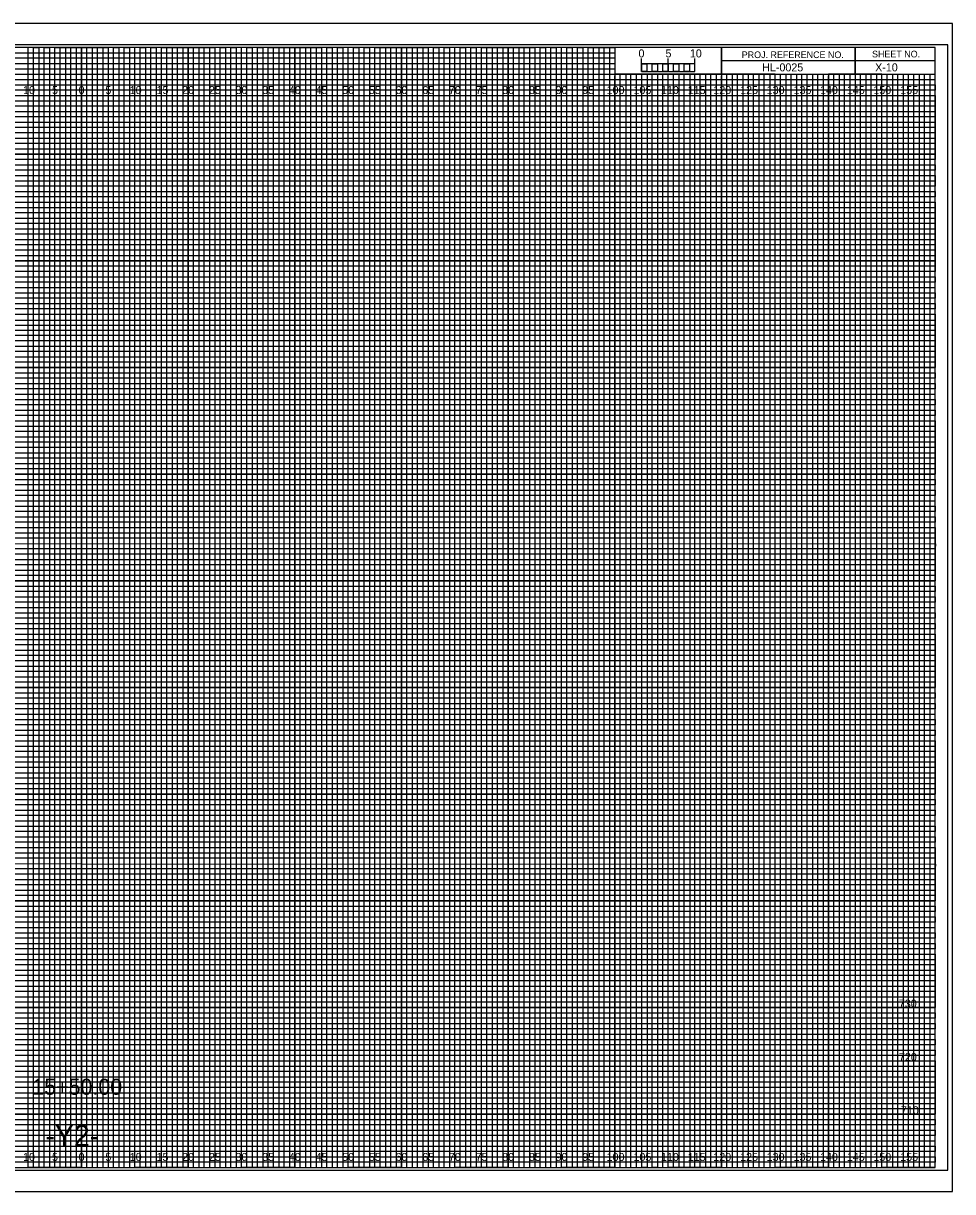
# Model space of a CAD drawing. Extents: x -13 to 323, y -5 to 654.
# Drawn here: x 149.1 to 323.3, y 435.5 to 654.5 of the extents above; entities that cross this region are included whole.
import ezdxf

# ---------------------------------------------------------------- set-up
doc = ezdxf.new("R2010")
doc.units = 0
for name, color, linetype in [('Exist CMT Pavement', 7, 'Continuous'), ('Exist Cross Section Cell', 7, 'Continuous'), ('Exist XS Center Line Elevation Label', 7, 'Continuous'), ('Exist XS Ground Line', 7, 'Continuous'), ('Prop CMT Pvmt Course 1', 7, 'Continuous'), ('Prop CMT Pvmt Course 1 Wedge', 7, 'Continuous'), ('Prop CMT Pvmt Course 2', 7, 'Continuous'), ('Prop CMT Pvmt Course 3', 7, 'Continuous'), ('Prop CMT Pvmt Surface', 7, 'Continuous'), ('Prop CMT Pvmt Surface Shoulder', 7, 'Continuous'), ('Prop CMT Pvmt Wedge Surface 1', 7, 'Continuous'), ('Prop CMT Shld Paved Course 1', 7, 'Continuous'), ('Prop CMT Shld Paved Course 2', 7, 'Continuous'), ('Prop CMT Shld Paved Course 3', 7, 'Continuous'), ('Prop CMT Slope Grass', 7, 'Continuous'), ('Prop CMT Subgrade Earthwork', 7, 'Continuous'), ('Scratch_Level_1', 7, 'Continuous')]:
    doc.layers.add(name, color=color, linetype=linetype)

msp = doc.modelspace()

# ---------------------------------------------------------------- linework, layer by layer
at = {"layer": 'Exist XS Center Line Elevation Label'}
for points in [[(145, 440), (155, 440), (155, 650), (165, 650), (165, 440), (175, 440), (175, 650), (185, 650), (185, 440), (195, 440), (195, 650), (205, 650), (205, 440), (215, 440), (215, 650), (225, 650), (225, 440), (235, 440), (235, 650), (245, 650), (245, 440), (255, 440), (255, 650), (259.93, 650), (260, 650), (260, 645), (264.99, 645), (264.99, 440), (275, 440), (275, 645), (285, 645), (285, 440), (295, 440), (295, 645), (305, 645), (305, 440), (315, 440), (315, 645)], [(0, 645), (275, 645)], [(0, 625), (320, 625), (320, 635), (0, 635)], [(0, 605), (320, 605), (320, 615), (0, 615)], [(0, 585), (320, 585), (320, 595), (0, 595)], [(0, 565), (320, 565), (320, 575), (0, 575)], [(0, 545), (320, 545), (320, 555), (0, 555)], [(0, 525), (320, 525), (320, 535), (0, 535)], [(0, 505), (320, 505), (320, 515), (0, 515)], [(0, 485), (320, 485), (320, 495), (0, 495)], [(0, 465), (320, 465), (320, 475), (0, 475)], [(0, 445), (320, 445), (320, 455), (0, 455)]]:
    msp.add_lwpolyline(points, dxfattribs=at)
at = {"layer": 'Exist XS Ground Line'}
for p, q in [((150, 650), (140, 650)), ((150, 440), (150, 650)), ((170, 650), (160, 650)), ((160, 650), (160, 440)), ((170, 440), (170, 650)), ((190, 650), (180, 650)), ((180, 650), (180, 440)), ((190, 440), (190, 650)), ((210, 650), (200, 650)), ((200, 650), (200, 440)), ((210, 440), (210, 650)), ((230, 650), (220, 650)), ((220, 650), (220, 440)), ((230, 440), (230, 650)), ((250, 650), (240, 650)), ((240, 650), (240, 440)), ((250, 440), (250, 650)), ((260, 650), (260, 440)), ((270, 440), (270, 645)), ((290, 645), (280, 645)), ((280, 645), (280, 440)), ((290, 440), (290, 645)), ((310, 645), (300, 645)), ((300, 645), (300, 440)), ((310, 440), (310, 645)), ((160, 440), (150, 440)), ((180, 440), (170, 440)), ((200, 440), (190, 440)), ((220, 440), (210, 440)), ((240, 440), (230, 440)), ((260, 440), (250, 440)), ((280, 440), (270, 440)), ((300, 440), (290, 440)), ((320, 440), (310, 440)), ((320, 440), (320, 440))]:
    msp.add_line(p, q, dxfattribs=at)
for points in [[(0, 640), (320, 640), (320, 630), (0, 630)], [(0, 620), (320, 620), (320, 610), (0, 610)], [(0, 600), (320, 600), (320, 590), (0, 590)], [(0, 580), (320, 580), (320, 570), (0, 570)], [(0, 560), (320, 560), (320, 550), (0, 550)], [(0, 540), (320, 540), (320, 530), (0, 530)], [(0, 520), (320, 520), (320, 510), (0, 510)], [(0, 500), (320, 500), (320, 490), (0, 490)], [(0, 480), (320, 480), (320, 470), (0, 470)], [(0, 460), (320, 460), (320, 450), (0, 450)]]:
    msp.add_lwpolyline(points, dxfattribs=at)
at = {"layer": 'Prop CMT Pvmt Course 2'}
msp.add_lwpolyline([(-13.4, 435.5), (323.3, 435.5), (323.3, 654.5), (-13.4, 654.5)], close=True, dxfattribs=at)
at = {"layer": 'Prop CMT Pvmt Course 3'}
msp.add_lwpolyline([(-10.8, 439.5), (322.4, 439.5), (322.4, 650.5), (-10.8, 650.5)], close=True, dxfattribs=at)
msp.add_lwpolyline([(-10.8, 439.5), (322.4, 439.5), (322.4, 650.5), (-10.8, 650.5)], close=True, dxfattribs=at)
at = {"layer": 'Prop CMT Pvmt Surface'}
for p, q in [((323.3, 654.5), (-13.4, 654.5)), ((323.3, 654.5), (-13.4, 654.5)), ((-13.4, 435.5), (323.3, 435.5)), ((-13.4, 435.5), (323.3, 435.5))]:
    msp.add_line(p, q, dxfattribs=at)
at = {"layer": 'Prop CMT Shld Paved Course 1'}
for p, q in [((305, 650), (305, 645)), ((305, 645), (305, 650)), ((280, 647.5), (280, 645)), ((320, 647.49), (280, 647.49)), ((280, 645), (320, 645))]:
    msp.add_line(p, q, dxfattribs=at)
for points in [[(320, 650), (0, 650), (0, 440), (320, 440)], [(280, 650), (260, 650), (260, 645.03), (280, 645.03)], [(320, 650), (280, 650), (280, 645), (320, 645)]]:
    msp.add_lwpolyline(points, close=True, dxfattribs=at)
at = {"layer": 'Prop CMT Shld Paved Course 2'}
for p, q in [((267, 645), (266.01, 645)), ((266.01, 645), (266.01, 440)), ((267, 440), (267, 645)), ((269, 645), (268, 645)), ((268, 645), (268, 440)), ((269, 440), (269, 645)), ((266.01, 440), (265, 440)), ((268, 440), (267, 440))]:
    msp.add_line(p, q, dxfattribs=at)
for points in [[(150, 440), (151, 440), (151, 650), (152, 650), (152, 440)], [(152, 440), (153, 440), (153, 650), (154, 650), (154, 440)], [(155, 440), (156, 440), (156, 650), (157, 650), (157, 440)], [(157, 440), (158, 440), (158, 650), (159, 650), (159, 440)], [(160, 440), (161, 440), (161, 650), (162, 650), (162, 440)], [(162, 440), (163, 440), (163, 650), (164, 650), (164, 440)], [(165, 440), (166, 440), (166, 650), (167, 650), (167, 440)], [(167, 440), (168, 440), (168, 650), (169, 650), (169, 440)], [(170, 440), (171, 440), (171, 650), (172, 650), (172, 440)], [(172, 440), (173, 440), (173, 650), (174, 650), (174, 440)], [(175, 440), (176, 440), (176, 650), (177, 650), (177, 440)], [(177, 440), (178, 440), (178, 650), (179, 650), (179, 440)], [(180, 440), (181, 440), (181, 650), (182, 650), (182, 440)], [(182, 440), (183, 440), (183, 650), (184, 650), (184, 440)], [(185, 440), (186, 440), (186, 650), (187, 650), (187, 440)], [(187, 440), (188, 440), (188, 650), (189, 650), (189, 440)], [(190, 440), (191, 440), (191, 650), (192, 650), (192, 440)], [(192, 440), (193, 440), (193, 650), (194, 650), (194, 440)], [(195, 440), (196, 440), (196, 650), (197, 650), (197, 440)], [(197, 440), (198, 440), (198, 650), (199, 650), (199, 440)], [(200, 440), (201, 440), (201, 650), (202, 650), (202, 440)], [(202, 440), (203, 440), (203, 650), (204, 650), (204, 440)], [(205, 440), (206, 440), (206, 650), (207, 650), (207, 440)], [(207, 440), (208, 440), (208, 650), (209, 650), (209, 440)], [(210, 440), (211, 440), (211, 650), (212, 650), (212, 440)], [(212, 440), (213, 440), (213, 650), (214, 650), (214, 440)], [(215, 440), (216, 440), (216, 650), (217, 650), (217, 440)], [(217, 440), (218, 440), (218, 650), (219, 650), (219, 440)], [(220, 440), (221, 440), (221, 650), (222, 650), (222, 440)], [(222, 440), (223, 440), (223, 650), (224, 650), (224, 440)], [(225, 440), (226, 440), (226, 650), (227, 650), (227, 440)], [(227, 440), (228, 440), (228, 650), (229, 650), (229, 440)], [(230, 440), (231, 440), (231, 650), (232, 650), (232, 440)], [(232, 440), (233, 440), (233, 650), (234, 650), (234, 440)], [(235, 440), (236, 440), (236, 650), (237, 650), (237, 440)], [(237, 440), (238, 440), (238, 650), (239, 650), (239, 440)], [(240, 440), (241, 440), (241, 650), (242, 650), (242, 440)], [(242, 440), (243, 440), (243, 650), (244, 650), (244, 440)], [(245, 440), (246, 440), (246, 650), (247, 650), (247, 440)], [(247, 440), (248, 440), (248, 650), (249, 650), (249, 440)], [(250, 440), (251, 440), (251, 650), (252, 650), (252, 440)], [(252, 440), (253, 440), (253, 650), (254, 650), (254, 440)], [(255, 440), (256, 440), (256, 650), (257, 650), (257, 440)], [(257, 440), (258, 440), (258, 650), (259, 650), (259, 440)], [(260, 440), (261, 440), (261, 645), (262.02, 645), (262.02, 440)], [(262, 440), (263, 440), (263, 645), (263.99, 645), (263.99, 440)], [(270, 440), (270.98, 440), (270.98, 645), (272, 645), (272, 440)], [(272, 440), (273, 440), (273, 645), (274.05, 645), (274.05, 440)], [(275, 440), (276, 440), (276, 645), (277, 645), (277, 440)], [(277, 440), (278, 440), (278, 645), (279, 645), (279, 440)], [(280, 440), (281, 440), (281, 645), (282, 645), (282, 440)], [(282, 440), (283, 440), (283, 645), (284, 645), (284, 440)], [(285, 440), (286, 440), (286, 645), (287, 645), (287, 440)], [(287, 440), (288, 440), (288, 645), (289, 645), (289, 440)], [(290, 440), (291, 440), (291, 645), (292, 645), (292, 440)], [(292, 440), (293, 440), (293, 645), (294, 645), (294, 440)], [(295, 440), (296, 440), (296, 645), (297, 645), (297, 440)], [(297, 440), (298, 440), (298, 645), (299, 645), (299, 440)], [(300, 440), (301, 440), (301, 645), (302, 645), (302, 440)], [(302, 440), (303, 440), (303, 645), (304, 645), (304, 440)], [(305, 440), (306, 440), (306, 645), (307, 645), (307, 440)], [(307, 440), (308, 440), (308, 645), (309, 645), (309, 440)], [(310, 440), (311, 440), (311, 645), (312, 645), (312, 440)], [(312, 440), (313, 440), (313, 645), (314, 645), (314, 440)], [(315, 440), (316, 440), (316, 645), (317, 645), (317, 440)], [(317, 440), (318, 440), (318, 645), (319, 645), (319, 440)]]:
    msp.add_lwpolyline(points, dxfattribs=at)
at = {"layer": 'Prop CMT Shld Paved Course 3'}
for p, q in [((265, 645.49), (265, 647.9)), ((265, 646.9), (265, 647.9)), ((270, 645.49), (270, 647.9)), ((275, 645.49), (275, 647.9)), ((275, 646.9), (275, 647.9))]:
    msp.add_line(p, q, dxfattribs=at)
for points in [[(275, 646.9), (265, 646.9), (265, 645.49), (275, 645.49)], [(265, 646.9), (266, 646.9), (266, 645.49), (265, 645.49)], [(267, 646.9), (268, 646.9), (268, 645.49), (267, 645.49)], [(269, 646.9), (270, 646.9), (270, 645.49), (269, 645.49)], [(271, 646.9), (272, 646.9), (272, 645.49), (271, 645.49)], [(273, 646.9), (274, 646.9), (274, 645.49), (273, 645.49)]]:
    msp.add_lwpolyline(points, close=True, dxfattribs=at)
at = {"layer": 'Prop CMT Subgrade Earthwork'}
for p, q in [((150, 440), (150, 650)), ((150, 440), (150, 650)), ((160, 440), (160, 650)), ((160, 440), (160, 650)), ((170, 440), (170, 650)), ((170, 440), (170, 650)), ((180, 440), (180, 650)), ((180, 440), (180, 650)), ((190, 440), (190, 650)), ((190, 440), (190, 650)), ((200, 440), (200, 650)), ((200, 440), (200, 650)), ((210, 440), (210, 650)), ((210, 440), (210, 650)), ((220, 440), (220, 650)), ((220, 440), (220, 650)), ((230, 440), (230, 650)), ((230, 440), (230, 650)), ((240, 440), (240, 650)), ((240, 440), (240, 650)), ((250, 440), (250, 650)), ((250, 440), (250, 650)), ((260, 440), (260, 644.69)), ((260, 440), (260, 644.69)), ((270, 440), (270, 644.69)), ((270, 440), (270, 644.69)), ((280, 440), (280, 644.69)), ((280, 440), (280, 644.69)), ((290, 440), (290, 644.69)), ((290, 440), (290, 644.69)), ((300, 440), (300, 644.69)), ((300, 440), (300, 644.69)), ((310, 440), (310, 644.69)), ((310, 440), (310, 644.69)), ((0, 640), (320, 640)), ((0, 640), (320, 640)), ((0, 630), (320, 630)), ((0, 630), (320, 630)), ((0, 620), (320, 620)), ((0, 620), (320, 620)), ((0, 610), (320, 610)), ((0, 610), (320, 610)), ((0, 600), (320, 600)), ((0, 600), (320, 600)), ((0, 590), (320, 590)), ((0, 590), (320, 590)), ((0, 580), (320, 580)), ((0, 580), (320, 580)), ((0, 570), (320, 570)), ((0, 570), (320, 570)), ((0, 560), (320, 560)), ((0, 560), (320, 560)), ((0, 550), (320, 550)), ((0, 550), (320, 550)), ((0, 540), (320, 540)), ((0, 540), (320, 540)), ((0, 530), (320, 530)), ((0, 530), (320, 530)), ((0, 520), (320, 520)), ((0, 520), (320, 520)), ((0, 510), (320, 510)), ((0, 510), (320, 510)), ((0, 500), (320, 500)), ((0, 500), (320, 500)), ((0, 490), (320, 490)), ((0, 490), (320, 490)), ((0, 480), (320, 480)), ((0, 480), (320, 480)), ((0, 470), (320, 470)), ((0, 470), (320, 470)), ((0, 460), (320, 460)), ((0, 460), (320, 460)), ((0, 450), (320, 450)), ((0, 450), (320, 450))]:
    msp.add_line(p, q, dxfattribs=at)
at = {"layer": 'Scratch_Level_1'}
for p, q in [((0, 649), (260, 649)), ((260, 649), (260, 647.98)), ((260, 647.98), (0, 647.98)), ((0, 647), (260, 647)), ((260, 647), (260, 645.89)), ((260, 645.89), (0, 645.89)), ((0, 644), (320, 644))]:
    msp.add_line(p, q, dxfattribs=at)
for points in [[(0, 643), (270, 643), (320, 643), (320, 642), (0, 642)], [(0, 641), (320, 641), (320, 639), (0, 639)], [(0, 638), (320, 638), (320, 637), (0, 636.98)], [(0, 636), (320, 636), (320, 634), (0, 634)], [(0, 633), (320, 633), (320, 632), (0, 632)], [(0, 631), (320, 631), (320, 629), (0, 629)], [(0, 628), (320, 628), (320, 627), (0, 627)], [(0, 626), (320, 626), (320, 624), (0, 624)], [(0, 623), (320, 623), (320, 622), (0, 622)], [(0, 621), (320, 621), (320, 619), (0, 619)], [(0, 618), (320, 618), (320, 617), (0, 617)], [(0, 616), (320, 616), (320, 613.95), (320, 613), (320, 612), (0, 612)], [(0, 614), (320, 614), (320, 613), (0, 613)], [(0, 611), (320, 611), (320, 609), (0, 609.03)], [(0, 609.03), (320, 609), (320, 608), (0, 608)], [(0, 607), (320, 607), (320, 606), (0, 606)], [(0, 604), (320, 604), (320, 603), (0, 603)], [(0, 602), (320, 602), (320, 601), (0, 601)], [(-0.07, 598.89), (320, 598.89), (320, 597.88), (-0.07, 597.88)], [(0, 597), (320, 597), (320, 596), (0, 596)], [(0, 594), (320, 594), (320, 593), (0, 593)], [(0, 592), (320, 592), (320, 591), (0, 591)], [(0, 589), (320, 589), (320, 588), (0, 588)], [(0, 587), (320, 587), (320, 586), (0, 586)], [(0, 584), (320, 584), (320, 583), (0, 583)], [(0, 582), (320, 582), (320, 581), (0, 581)], [(0, 579), (320, 579), (319.99, 577.98), (0, 578)], [(0, 577), (320, 577), (320, 576), (0, 576)], [(0, 574), (320, 574), (320, 573), (0, 573)], [(0, 572), (320, 572), (320, 571), (0, 571)], [(0, 569), (320, 569), (320, 568), (0, 568)], [(0, 567), (320, 567), (320, 566), (0, 566)], [(0, 564), (320, 564), (320, 563), (0, 563)], [(0, 562), (320, 562), (320, 561), (0, 561)], [(0, 559), (320, 559), (320, 558), (0, 558)], [(0, 556.99), (320.07, 556.91), (320, 556), (0, 556)], [(0, 554), (320, 554), (320, 553), (0, 553)], [(0, 552), (320, 552), (320, 551), (0, 551)], [(0, 549), (320, 549), (320, 548), (0, 548)], [(0, 547), (320, 547), (320, 546), (0, 546)], [(0, 544), (320, 544), (320, 543), (0, 543)], [(0, 542), (320, 542), (320, 541), (0, 541)], [(0, 539), (320, 539), (320, 538), (0, 538)], [(0, 537), (320, 537), (320, 536), (0, 536)], [(0, 534), (320, 534), (320, 533), (0, 533)], [(0, 532), (320, 532), (320, 531), (0, 531)], [(0, 529), (320, 529), (320, 528), (0, 528)], [(0, 527), (320, 527), (320, 526), (0, 526)], [(0, 524), (320, 524), (320, 523), (0, 523)], [(0, 522), (320, 522), (320, 521), (0, 521)], [(0, 519), (320, 519), (319.99, 517.98), (0, 518)], [(0, 517), (320, 517), (320, 516), (0, 516)], [(0, 514), (320, 514), (320, 513), (0, 513)], [(0, 512), (320, 512), (320, 511), (0, 511)], [(0, 509), (320, 509), (320, 508), (0, 508)], [(0, 507), (320, 507), (320, 506), (0, 506)], [(0, 504), (320, 504), (320, 503), (0, 503)], [(0, 502), (320, 502), (320, 501), (0, 501)], [(0, 499), (320, 499), (320, 498), (0, 498)], [(0, 496.99), (320.07, 496.91), (320, 496), (0, 496)], [(0, 494), (320, 494), (320, 493), (0, 493)], [(0, 492), (320, 492), (320, 491), (0, 491)], [(0, 489), (320, 489), (320, 488), (0, 488)], [(0, 487), (320, 487), (320, 486), (0, 486)], [(0, 484), (320, 484), (320, 483), (0, 483)], [(0, 482), (320, 482), (320, 481), (0, 481)], [(0, 479), (320, 479), (320, 478), (0, 478)], [(0, 477), (320, 477), (320, 476), (0, 476)], [(0, 474), (320, 474), (320, 473), (0, 473)], [(0, 472), (320, 472), (320, 471), (0, 471)], [(0, 469), (320, 469), (320, 468), (0, 468)], [(0, 467), (320, 467), (320, 466), (0, 466)], [(0, 464), (320, 464), (320, 463), (0, 463)], [(0, 462), (320, 462), (320, 461), (0, 461)], [(0, 459), (320, 459), (320, 458), (0, 458)], [(0, 457), (320, 457), (320, 456), (0, 456)], [(0, 454), (320, 454), (320, 453), (0, 453)], [(0, 452), (320, 452), (320, 451), (0, 451)], [(0, 449), (320, 449), (320, 448), (0, 448)], [(0, 447), (320, 447), (320, 446), (0, 446)], [(0, 444), (320, 444), (320, 443), (0, 443)], [(0, 442), (320, 442), (320, 441), (0, 441)]]:
    msp.add_lwpolyline(points, dxfattribs=at)

# ---------------------------------------------------------------- texts
at = {"layer": 'Exist CMT Pavement'}
msp.add_text('-Y2-', height=4, dxfattribs=at).set_placement((153.21, 444))
at = {"layer": 'Exist Cross Section Cell'}
for s, p in [('10', (149.04, 641.25)), ('5', (154.47, 641.25)), ('0', (159.45, 641.25)), ('0', (159.45, 641.25)), ('5', (164.47, 641.25)), ('10', (169.04, 641.25)), ('15', (174.06, 641.25)), ('20', (178.86, 641.25)), ('25', (183.88, 641.25)), ('30', (188.86, 641.25)), ('35', (193.88, 641.25)), ('40', (198.86, 641.25)), ('45', (203.88, 641.25)), ('50', (208.86, 641.25)), ('55', (213.88, 641.25)), ('60', (218.86, 641.25)), ('65', (223.88, 641.25)), ('70', (228.86, 641.25)), ('75', (233.88, 641.25)), ('80', (238.86, 641.25)), ('85', (243.88, 641.25)), ('90', (248.86, 641.25)), ('95', (253.88, 641.25)), ('100', (258.44, 641.25)), ('105', (263.47, 641.25)), ('110', (268.62, 641.25)), ('115', (273.65, 641.25)), ('120', (278.44, 641.25)), ('125', (283.47, 641.25)), ('130', (288.44, 641.25)), ('135', (293.47, 641.25)), ('140', (298.44, 641.25)), ('145', (303.47, 641.25)), ('150', (308.44, 641.25)), ('155', (313.47, 641.25)), ('10', (149.04, 441.25)), ('5', (154.47, 441.25)), ('0', (159.45, 441.25)), ('0', (159.45, 441.25)), ('5', (164.47, 441.25)), ('10', (169.04, 441.25)), ('15', (174.06, 441.25)), ('20', (178.86, 441.25)), ('25', (183.88, 441.25)), ('30', (188.86, 441.25)), ('35', (193.88, 441.25)), ('40', (198.86, 441.25)), ('45', (203.88, 441.25)), ('50', (208.86, 441.25)), ('55', (213.88, 441.25)), ('60', (218.86, 441.25)), ('65', (223.88, 441.25)), ('70', (228.86, 441.25)), ('75', (233.88, 441.25)), ('80', (238.86, 441.25)), ('85', (243.88, 441.25)), ('90', (248.86, 441.25)), ('95', (253.88, 441.25)), ('100', (258.44, 441.25)), ('105', (263.47, 441.25)), ('110', (268.62, 441.25)), ('115', (273.65, 441.25)), ('120', (278.44, 441.25)), ('125', (283.47, 441.25)), ('130', (288.44, 441.25)), ('135', (293.47, 441.25)), ('140', (298.44, 441.25)), ('145', (303.47, 441.25)), ('150', (308.44, 441.25)), ('155', (313.47, 441.25))]:
    msp.add_text(s, height=1.5, dxfattribs=at).set_placement(p)
at = {"layer": 'Prop CMT Pvmt Course 1'}
msp.add_text('15+50.00', height=3, dxfattribs=at).set_placement((150.77, 453.66))
at = {"layer": 'Prop CMT Pvmt Course 1 Wedge'}
msp.add_text('HL-0025', height=1.5, dxfattribs=at).set_placement((287.6, 645.5))
at = {"layer": 'Prop CMT Pvmt Surface Shoulder'}
for s, p in [('730', (313.22, 470)), ('720', (313.23, 460)), ('710', (313.61, 450))]:
    msp.add_text(s, height=1.5, dxfattribs=at).set_placement(p)
at = {"layer": 'Prop CMT Pvmt Wedge Surface 1'}
for s, p in [('5', (269.47, 648.12)), ('10', (274.04, 648.12))]:
    msp.add_text(s, height=1.5, dxfattribs=at).set_placement(p)
at = {"layer": 'Prop CMT Shld Paved Course 1'}
for s, p in [('PROJ. REFERENCE NO.', (283.77, 647.99)), ('SHEET NO.', (308.19, 648.12))]:
    msp.add_text(s, height=1.25, dxfattribs=at).set_placement(p)
at = {"layer": 'Prop CMT Shld Paved Course 3'}
msp.add_text('0', height=1.5, dxfattribs=at).set_placement((264.41, 648.12))
at = {"layer": 'Prop CMT Slope Grass'}
msp.add_text('X-10', height=1.5, dxfattribs=at).set_placement((308.77, 645.5))

doc.saveas('drawing.dxf')
